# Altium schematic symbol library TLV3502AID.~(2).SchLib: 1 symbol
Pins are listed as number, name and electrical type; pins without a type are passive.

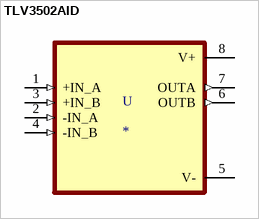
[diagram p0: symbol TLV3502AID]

## TLV3502AID
designator U
4.5ns Rail-to-Rail Comparator; MF: Texas Instruments; MP: TLV3502AID
footprint TLV3502AID
pins: 1 +IN_A (in), 2 -IN_A (in), 3 +IN_B (in), 4 -IN_B (in), 5 V- (power), 6 OUTB (out), 7 OUTA (out), 8 V+ (power)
